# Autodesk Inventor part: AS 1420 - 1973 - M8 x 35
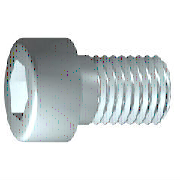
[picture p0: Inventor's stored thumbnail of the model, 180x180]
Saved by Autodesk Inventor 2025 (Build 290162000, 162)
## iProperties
Created: 2024-01
Part Number: AS 1420 - 1973 - M8 x 35
Material: Acciaio, Dolce
Description: Viti con esagono incassato metriche ISO
Document SubType Name: Modeling
Standard: AS 1420 - 1973
Designer: R5800u
Standards Organization: AS
Language: it-IT
Size Designation: M8 x 35
Categories: <MemberInstance><Categories><Category DisplayName="Elementi di fissaggio" InternalName="e4da775c-781d-43d5-af7c-5136215cf5a6" Mnemonic="FSTN"><Category DisplayN
Density: 7.85 g/cm^3
Appearance: Semilucidato
IsCustomPart: 0
Author: R5800u
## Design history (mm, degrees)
body "Solid1"
workplane "Work Plane1"
fillet "Fillet2" dims "d30" = 0.1 (= R)
revolve "Corpo" stored, may be unused: angle "d10" = 90 deg
sketch "Schizzo2"
  geometry: L1 (0, -9.1)-(0, 9.1) reference; L2 (-9.1, 0)-(9.1, 0) reference; L3 (3.464, 0)-(1.732, -3); L4 (1.732, -3)-(-1.732, -3); L5 (-1.732, -3)-(-3.464, 0); L6 (-3.464, 0)-(-1.732, 3); L7 (-1.732, 3)-(1.732, 3); L8 (1.732, 3)-(3.464, 0); 2 further points
  constraints: 12 end point, 1 coincident, 1 horizontal alignment, 1 point on line, 12 other
extrude "Intaglio" join sketch "Schizzo2" stored distance "d11" = 10; taper "d12" = 0 deg
fillet "Raccordo1" dims "d17" = 0.8 (= RR)
feature "Filettatura" dims "d13" = 22 (= GEL), "d14" = 0
chamfer "Smusso1" distance "d15" = 0.76681 (= -0.5 x SPD + 0.5 x GD); stored, may be unused: second distance "d16" = 0.76681 (= GUL), angle "d27" = 45 deg
sketch "Schizzo1"
  geometry: L1 (-2, 0)-(35, 0); L2 (35, 0)-(35, 4); L3 (35, 4)-(13, 4); L4 (13, 4)-(12.233, 4); L5 (12.233, 4)-(0, 4); L6 (0, 4)-(0, 6.5); L7 (0, 6.5)-(-8, 6.5); L8 (-8, 6.5)-(-8, 3.464); L9 (-8, 3.464)-(-4, 3.464); L10 (-4, 3.464)-(-2, 0); L11 (-16.6, 0)-(43.6, 0) reference; L12 (0, -1.3)-(0, 7.8) reference; L13 (13, 4)-(0, 4)
  constraints: 22 end point, 6 parallel, 2 collinear, 2 perpendicular, 1 horizontal, 1 point on line
  dimensions: "d1" = 22 distance from line of L3.end L2 (= GEL); "d2" = 0.76691 distance of L4.end L3.end (computed from GAL); "d3" = 8 distance between parallel lines of L8 L6 (= KOH); "d4" = 4 distance of L8.end L9.end (= INTI); "d5" = 60 deg angle of L10 L1; "d6" = 8 diameter of L3 L1 (= GD); "d7" = 8 diameter of L5 L1 (= BDM); "d8" = 6.9282 diameter of L9 L1 (= 1.1547 x SW); "d9" = 13 diameter of L7 L1 (= KOD); "d26" = 35 distance between parallel lines of L12 L2 (= NLG)
other parameters: "GD" = 8 (= NND) [user parameter; used in 2 equation terms], "NLG" = 35 [user parameter; used in 1 equation term], "GEL" = 22 [user parameter; used in 2 equation terms], "KOD" = 13 [user parameter; used in 1 equation term], "KOH" = 8 (= NND) [user parameter; used in 1 equation term], "INTI" = 4 [user parameter; used in 1 equation term], "GAL" = 0.76681 (= 0.61345 x PTC) [user parameter; used in 1 equation term], "GUL" = 0.76681 (= 0.61345 x PTC) [user parameter; used in 1 equation term], "BDM" = 8 (= NND) [user parameter; used in 1 equation term], "SW" = 6 [user parameter; used in 2 equation terms], "RR" = 0.8 (= 0.1 x NND) [user parameter; used in 1 equation term], "SPD" = 6.46637 (= NND - 1.2269 x PTC) [user parameter; used in 1 equation term], "d19" = 0, "d28" = 0, "d29" = 0, "R" = 0.1 [user parameter; used in 1 equation term], "PHH" = 0.2 [user parameter], "GD1" = 6.46637 (= THREADDIA - 1.2269 x PTC) [user parameter], "THREADDIA" = 8 [user parameter; used in 1 equation term], "FAWI" = 45 deg [user parameter], "TPU" = 8 (computed from PTC) [user parameter], "PTC" = 1.25 [user parameter; used in 5 equation terms], "KOH1" = 7.2 [user parameter], "NND" = 8 [user parameter; used in 5 equation terms], "TOA" = 30 deg [user parameter], "E0" = 6.93 (= 1.155 x SW) [user parameter]
